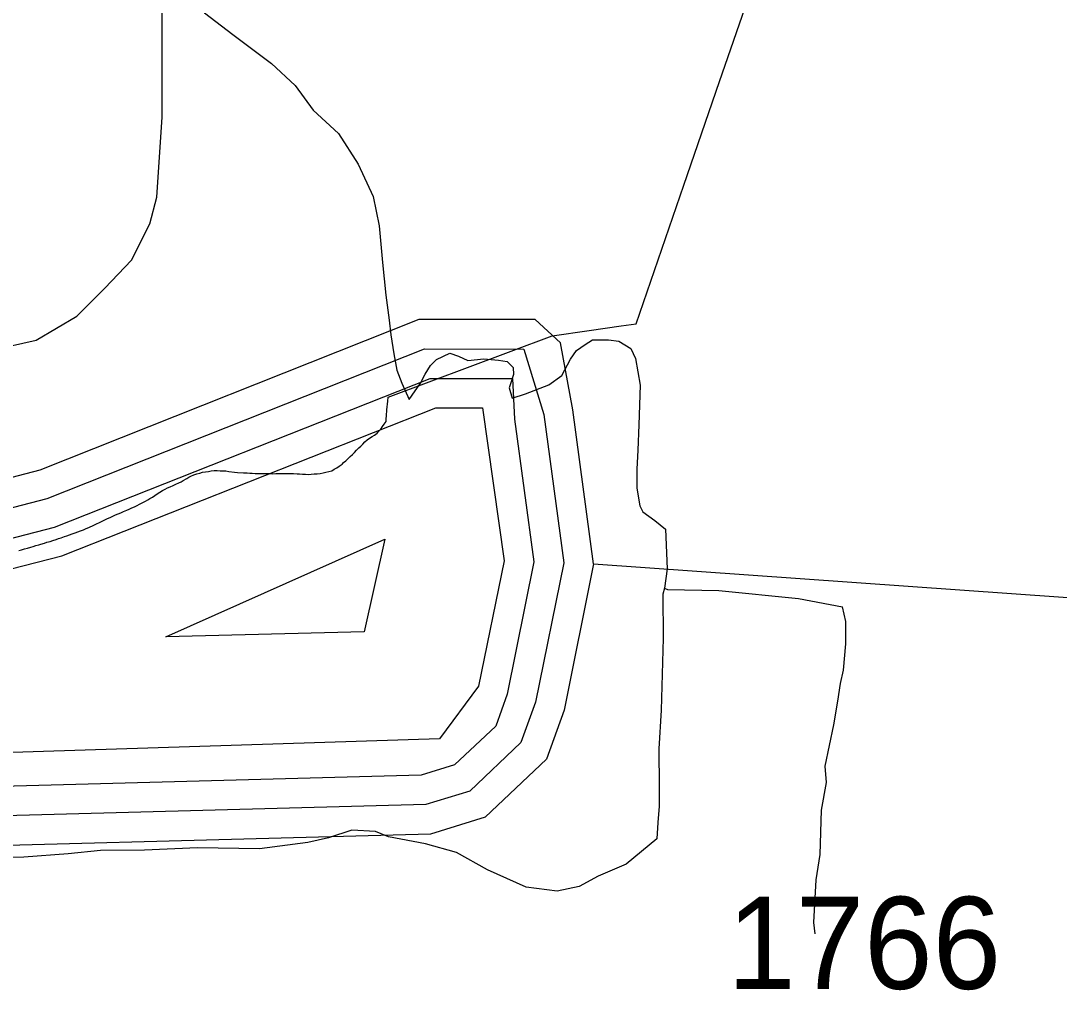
# Model space of a CAD drawing. Extents: x 2315291 to 2336543, y 597177 to 615230.
# Drawn here: x 2329009 to 2330419, y 597453 to 598769 of the extents above; entities that cross this region are included whole.
import ezdxf

# ---------------------------------------------------------------- set-up
doc = ezdxf.new("R2010")
doc.units = 0
for name, color, linetype in [('Exist Boundary Political City Limit New', 7, 'Continuous'), ('Exist Hydrographic Buffer Line', 7, 'Continuous'), ('Exist Hydrographic Creek Single Shore', 7, 'Continuous'), ('Exist Hydrographic Lake Shore', 7, 'Continuous'), ('Exist Hydrographic Misc Water Feature', 7, 'Continuous'), ('Exist Road Non-System Type 51', 7, 'Continuous'), ('Exist Road Secondary Type 51 Number Label', 7, 'Continuous'), ('Map Preparation Boundary City Limit Buffer Line', 7, 'Continuous')]:
    doc.layers.add(name, color=color, linetype=linetype)

msp = doc.modelspace()

# ---------------------------------------------------------------- linework, layer by layer
at = {"layer": 'Exist Boundary Political City Limit New'}
for points in [[(2329320, 598154.7), (2329323.2, 598154.6), (2329327.2, 598154.4), (2329335.2, 598154.1), (2329339.2, 598154.1), (2329343.2, 598154), (2329347.2, 598154), (2329350.5, 598153.9), (2329355.2, 598154), (2329359.2, 598154.1), (2329363.5, 598154.2), (2329367.5, 598154.3), (2329371.2, 598154.2), (2329379.2, 598154), (2329384, 598153.8), (2329387.2, 598153.6), (2329391.2, 598153.3), (2329395.2, 598153.1), (2329399.2, 598152.9), (2329403.2, 598153.2), (2329407.2, 598153.6), (2329411.2, 598153.9), (2329415.2, 598154.3), (2329419.2, 598155.1), (2329423.2, 598156), (2329427.2, 598157), (2329431, 598158), (2329434.2, 598159.9), (2329437.8, 598161.9), (2329441, 598164), (2329445.2, 598166.9), (2329445.8, 598167.4), (2329447.2, 598168.9), (2329450.2, 598171.6), (2329453.2, 598174.4), (2329456.2, 598177.2), (2329459.2, 598180.1), (2329462, 598182.9), (2329464.8, 598185.7), (2329468, 598189.1), (2329470.5, 598191.4), (2329473.2, 598194.2), (2329476, 598197.1), (2329479, 598199.8), (2329482.2, 598202), (2329485.8, 598204.2), (2329489, 598206.4), (2329492.5, 598208.8), (2329495, 598211.5), (2329497.5, 598214.5), (2329500, 598217.8), (2329502.2, 598221), (2329504.8, 598224.6), (2329505, 598228.6), (2329505.5, 598232.5), (2329506, 598240.5), (2329506.5, 598244.5), (2329506.8, 598248.5), (2329507.2, 598252.4), (2329507.8, 598257.6), (2329730.2, 598341.1), (2329780.5, 598348.1), (2329824, 598354.5), (2329844.5, 598357.1), (2329909.2, 598545.6), (2329957.5, 598686), (2330000, 598809.3)], [(2329006.2, 598049.8), (2329010, 598050.8), (2329014, 598051.9), (2329017.8, 598053), (2329022.5, 598054.4), (2329025.5, 598055.2), (2329029.2, 598056.4), (2329033.2, 598057.6), (2329036.2, 598058.5), (2329040.8, 598059.8), (2329044, 598060.8), (2329048.5, 598062.1), (2329052.2, 598063.3), (2329057, 598064.8), (2329060, 598065.8), (2329063.8, 598067), (2329068.2, 598068.6), (2329071.2, 598069.6), (2329075, 598070.9), (2329078.8, 598072.2), (2329082.5, 598073.6), (2329086.2, 598075), (2329090, 598076.4), (2329093.8, 598077.8), (2329097.5, 598079.4), (2329101.2, 598081), (2329108.2, 598084.2), (2329111.8, 598086), (2329115.5, 598087.8), (2329119.2, 598089.6), (2329122.8, 598091.2), (2329126.5, 598093), (2329130, 598094.6), (2329133.8, 598096.2), (2329137.5, 598097.9), (2329141, 598099.4), (2329144.8, 598101), (2329148.5, 598102.5), (2329152.8, 598104.4), (2329155.8, 598105.8), (2329159.5, 598107.4), (2329163, 598109.1), (2329167, 598110.9), (2329170.2, 598112.6), (2329173.8, 598114.4), (2329178.2, 598116.6), (2329181.5, 598118.3), (2329184.2, 598120.1), (2329187.8, 598122.3), (2329191, 598124.5), (2329194, 598126.5), (2329197.8, 598128.8), (2329201.2, 598130.9), (2329204.8, 598132.8), (2329208.2, 598134.8), (2329211.8, 598136.3), (2329215.5, 598137.9), (2329219.2, 598139.5), (2329223.5, 598141.5), (2329226.5, 598143.1), (2329229.5, 598144.7), (2329234.2, 598147.5), (2329236.8, 598149.1), (2329239.8, 598150.8), (2329244, 598152.4), (2329247.8, 598153.6), (2329251.8, 598154.8), (2329255.5, 598155.8), (2329259.5, 598156.4), (2329263.5, 598157), (2329267.5, 598157.6), (2329271.5, 598158.1), (2329275.5, 598158.1), (2329279.5, 598158), (2329283.2, 598157.8), (2329287.2, 598157.6), (2329291.2, 598157), (2329299.2, 598156), (2329303.2, 598155.6), (2329311.2, 598155.1), (2329316.2, 598154.9), (2329320, 598154.7)]]:
    msp.add_lwpolyline(points, dxfattribs=at)
at = {"layer": 'Exist Hydrographic Buffer Line'}
for points in [[(2327876.1, 597659.7), (2327603.6, 597689.7), (2327215.4, 597902.1), (2327052.4, 598101.4), (2327002.2, 598173.5), (2326898.6, 598294.2), (2326753.7, 598385.8), (2326773.2, 598452.7), (2326913, 598468.3), (2326998.1, 598441.3), (2327236.2, 598271), (2327736.7, 598041), (2328045.1, 597974.9), (2328605.7, 598006.2), (2329044.5, 598120.1), (2329557.1, 598323.3), (2329691.7, 598323.1), (2329718.9, 598234.2), (2329746, 598032.9), (2329707.7, 597843.9), (2329688, 597789), (2329618.7, 597723.2), (2329559, 597704.8), (2327876.1, 597659.7)], [(2327877.8, 597699.7), (2327615.9, 597728.6), (2327241.5, 597933.5), (2327084.4, 598125.5), (2327035.2, 598196.3), (2326929.2, 598320.2), (2326799.2, 598406.7), (2326910.1, 598427.2), (2326980, 598405), (2327213, 598238.5), (2327720.1, 598004.6), (2328036.9, 597935.8), (2328608.2, 597966.2), (2329054.8, 598081.4), (2329564.7, 598283.3), (2329676.3, 598283.2), (2329679.4, 598227.9), (2329705.4, 598034.3), (2329669.1, 597854.7), (2329653.7, 597811.4), (2329597.9, 597758.7), (2329552.4, 597744.7), (2327877.8, 597699.7)], [(2327879.4, 597739.8), (2327628.2, 597767.5), (2327267.3, 597964.8), (2327116.2, 598149.6), (2327067.8, 598219.2), (2326959.3, 598346.3), (2327189.6, 598206), (2327703.5, 597968.2), (2328028.7, 597896.6), (2328610.4, 597926.3), (2329064.6, 598042.6), (2329572.5, 598243.3), (2329635.9, 598243.1), (2329665, 598035.6), (2329630.3, 597865.5), (2329577.2, 597794.1), (2327879.4, 597739.8)], [(2329205.7, 597932.6), (2329503.2, 598065.1), (2329475.1, 597939.2), (2329205.7, 597932.6)]]:
    msp.add_lwpolyline(points, dxfattribs=at)
at = {"layer": 'Exist Hydrographic Creek Single Shore'}
msp.add_lwpolyline([(2329786.4, 598031.6), (2330494.4, 597981.5), (2330694.4, 597992.9), (2331363.4, 598456.3), (2331496.5, 598524.1), (2332070.5, 598622.7)], dxfattribs=at)
at = {"layer": 'Exist Hydrographic Lake Shore'}
for points in [[(2329786.4, 598031.6), (2329746.4, 597833.1), (2329722.4, 597766.4), (2329639.4, 597687.7), (2329565.3, 597664.9), (2327874.5, 597619.6), (2327591.5, 597650.8), (2327189.4, 597870.8), (2327020.4, 598077.3), (2326969.4, 598150.7), (2326868.5, 598268.1), (2326708.4, 598366.6), (2326750.7, 598472.2), (2326885.5, 598504.4)], [(2329786.4, 598031.6), (2329758.5, 598240.5), (2329741.5, 598331.7), (2329707.4, 598363.1), (2329549.4, 598363.3), (2329034.5, 598158.7), (2328603.4, 598046.1), (2328053.5, 598014.1), (2327753.5, 598077.4), (2327259.3, 598303.5), (2327016.3, 598477.5), (2326915.5, 598509.5), (2326885.5, 598504.4)]]:
    msp.add_lwpolyline(points, dxfattribs=at)
at = {"layer": 'Exist Hydrographic Misc Water Feature'}
for points in [[(2329187.6, 598862.6), (2329224.1, 598815.3), (2329258.4, 598779.4), (2329296.9, 598750), (2329349.4, 598710.5), (2329381.4, 598680.9), (2329406, 598647.3), (2329440.3, 598615.7), (2329466.9, 598574), (2329487.2, 598530), (2329495.4, 598490.2), (2329499.9, 598440.5), (2329504.7, 598396.4), (2329509.2, 598362.4), (2329511.2, 598342.2), (2329515.5, 598316.5), (2329519.4, 598294.4), (2329526, 598276.8), (2329536.2, 598254.6)], [(2329536.2, 598254.6), (2329551.4, 598277), (2329557.8, 598289), (2329565.1, 598300.9), (2329573.3, 598309), (2329591.2, 598317.3), (2329603.3, 598313.4), (2329615.6, 598307.5), (2329637.7, 598309.8), (2329657.4, 598308.1), (2329669.3, 598306.3), (2329677.3, 598298.2), (2329677.9, 598288.4), (2329673.6, 598276.1), (2329671.8, 598270.3), (2329675.9, 598256.3), (2329693.9, 598262.5), (2329725.7, 598274.7), (2329743.5, 598287), (2329755.2, 598309.2), (2329763.2, 598321), (2329775.1, 598329.3), (2329785.2, 598335.5), (2329806.9, 598335.5), (2329821, 598333.8), (2329837.2, 598324), (2329843.4, 598310.1), (2329849.8, 598274.3), (2329847.9, 598220.2), (2329846.5, 598186), (2329845.2, 598160.2), (2329845.2, 598134.3), (2329849.5, 598110.1), (2329853.4, 598102.2), (2329869.6, 598090.4), (2329884, 598078.5), (2329886.5, 598024.7), (2329883, 597998.4)], [(2329883, 597998.4), (2329880.7, 597990.6), (2329880.9, 597930.6), (2329878.3, 597832.8), (2329875.2, 597780.6), (2329875.4, 597728.7), (2329875.8, 597702.6), (2329873.7, 597680.6), (2329872.3, 597658.5), (2329830.9, 597624.2), (2329792.7, 597607.6), (2329767.1, 597593.7), (2329737.2, 597587.2), (2329695.1, 597592.8), (2329642.4, 597616.1), (2329600.6, 597639.8), (2329558.2, 597651.5), (2329508.3, 597661), (2329490.5, 597668.5), (2329458.5, 597670.1), (2329426.7, 597659.9), (2329398.4, 597653.6), (2329332.8, 597644.9), (2329248.7, 597646.1), (2329177, 597643.2), (2329116.9, 597642.4), (2329073.2, 597638.1), (2329012.9, 597633.4), (2328984.8, 597633.1)], [(2329883, 597998.4), (2329886.9, 597996.6), (2329956.8, 597995.4), (2330064.6, 597984.5), (2330124.7, 597973.3)], [(2330087.4, 597529.5), (2330085.4, 597545), (2330088.6, 597602.9), (2330094.4, 597636.9), (2330095.8, 597697.1), (2330103, 597735), (2330101.1, 597757.1), (2330112.6, 597813), (2330118.4, 597845.4), (2330121.9, 597869.2), (2330125.8, 597887.3), (2330129.2, 597923.2), (2330129, 597953.3), (2330124.7, 597973.3)]]:
    msp.add_lwpolyline(points, dxfattribs=at)
at = {"layer": 'Exist Road Non-System Type 51'}
msp.add_lwpolyline([(2328971, 598321.9), (2329029.9, 598335.2), (2329085, 598367.5), (2329123, 598405.6), (2329159.2, 598443.6), (2329183.9, 598493), (2329193.4, 598529.2), (2329201, 598637.6), (2329201, 598742.1), (2329201, 598848.6)], dxfattribs=at)
at = {"layer": 'Map Preparation Boundary City Limit Buffer Line'}
for points in [[(2329320, 598154.7), (2329323.2, 598154.6), (2329327.2, 598154.4), (2329335.2, 598154.1), (2329339.2, 598154.1), (2329343.2, 598154), (2329347.2, 598154), (2329350.5, 598153.9), (2329355.2, 598154), (2329359.2, 598154.1), (2329363.5, 598154.2), (2329367.5, 598154.3), (2329371.2, 598154.2), (2329379.2, 598154), (2329384, 598153.8), (2329387.2, 598153.6), (2329391.2, 598153.3), (2329395.2, 598153.1), (2329399.2, 598152.9), (2329403.2, 598153.2), (2329407.2, 598153.6), (2329411.2, 598153.9), (2329415.2, 598154.3), (2329419.2, 598155.1), (2329423.2, 598156), (2329427.2, 598157), (2329431, 598158), (2329434.2, 598159.9), (2329437.8, 598161.9), (2329441, 598164), (2329445.2, 598166.9), (2329445.8, 598167.4), (2329447.2, 598168.9), (2329450.2, 598171.6), (2329453.2, 598174.4), (2329456.2, 598177.2), (2329459.2, 598180.1), (2329462, 598182.9), (2329464.8, 598185.7), (2329468, 598189.1), (2329470.5, 598191.4), (2329473.2, 598194.2), (2329476, 598197.1), (2329479, 598199.8), (2329482.2, 598202), (2329485.8, 598204.2), (2329489, 598206.4), (2329492.5, 598208.8), (2329495, 598211.5), (2329497.5, 598214.5), (2329500, 598217.8), (2329502.2, 598221), (2329504.8, 598224.6), (2329505, 598228.6), (2329505.5, 598232.5), (2329506, 598240.5), (2329506.5, 598244.5), (2329506.8, 598248.5), (2329507.2, 598252.4), (2329507.8, 598257.6), (2329730.2, 598341.1), (2329780.5, 598348.1), (2329824, 598354.5), (2329844.5, 598357.1), (2329909.2, 598545.6), (2329957.5, 598686), (2330000, 598809.3)], [(2329006.2, 598049.8), (2329010, 598050.8), (2329014, 598051.9), (2329017.8, 598053), (2329022.5, 598054.4), (2329025.5, 598055.2), (2329029.2, 598056.4), (2329033.2, 598057.6), (2329036.2, 598058.5), (2329040.8, 598059.8), (2329044, 598060.8), (2329048.5, 598062.1), (2329052.2, 598063.3), (2329057, 598064.8), (2329060, 598065.8), (2329063.8, 598067), (2329068.2, 598068.6), (2329071.2, 598069.6), (2329075, 598070.9), (2329078.8, 598072.2), (2329082.5, 598073.6), (2329086.2, 598075), (2329090, 598076.4), (2329093.8, 598077.8), (2329097.5, 598079.4), (2329101.2, 598081), (2329108.2, 598084.2), (2329111.8, 598086), (2329115.5, 598087.8), (2329119.2, 598089.6), (2329122.8, 598091.2), (2329126.5, 598093), (2329130, 598094.6), (2329133.8, 598096.2), (2329137.5, 598097.9), (2329141, 598099.4), (2329144.8, 598101), (2329148.5, 598102.5), (2329152.8, 598104.4), (2329155.8, 598105.8), (2329159.5, 598107.4), (2329163, 598109.1), (2329167, 598110.9), (2329170.2, 598112.6), (2329173.8, 598114.4), (2329178.2, 598116.6), (2329181.5, 598118.3), (2329184.2, 598120.1), (2329187.8, 598122.3), (2329191, 598124.5), (2329194, 598126.5), (2329197.8, 598128.8), (2329201.2, 598130.9), (2329204.8, 598132.8), (2329208.2, 598134.8), (2329211.8, 598136.3), (2329215.5, 598137.9), (2329219.2, 598139.5), (2329223.5, 598141.5), (2329226.5, 598143.1), (2329229.5, 598144.7), (2329234.2, 598147.5), (2329236.8, 598149.1), (2329239.8, 598150.8), (2329244, 598152.4), (2329247.8, 598153.6), (2329251.8, 598154.8), (2329255.5, 598155.8), (2329259.5, 598156.4), (2329263.5, 598157), (2329267.5, 598157.6), (2329271.5, 598158.1), (2329275.5, 598158.1), (2329279.5, 598158), (2329283.2, 598157.8), (2329287.2, 598157.6), (2329291.2, 598157), (2329299.2, 598156), (2329303.2, 598155.6), (2329311.2, 598155.1), (2329316.2, 598154.9), (2329320, 598154.7)]]:
    msp.add_lwpolyline(points, dxfattribs=at)

# ---------------------------------------------------------------- texts
at = {"layer": 'Exist Road Secondary Type 51 Number Label'}
msp.add_text('1766', height=125, dxfattribs=at).set_placement((2329968, 597454.7))

doc.saveas('drawing.dxf')
